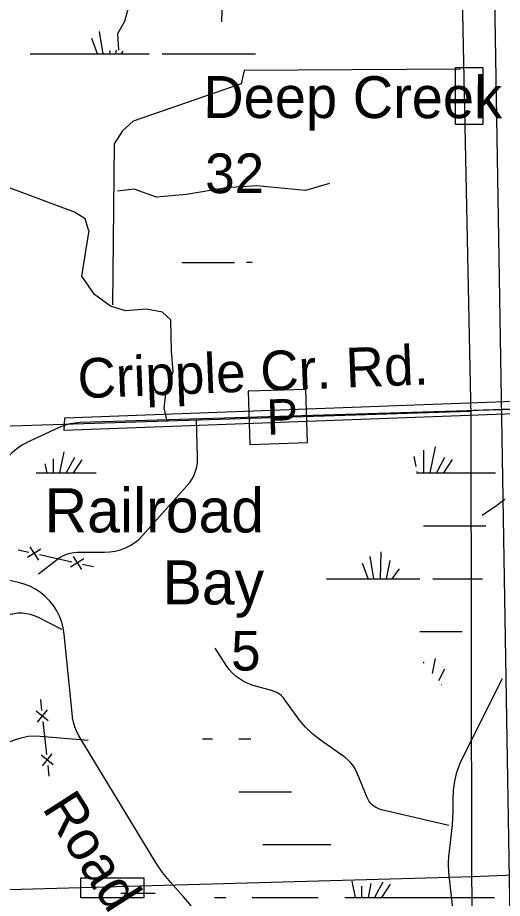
# Model space of a CAD drawing. Extents: x 2480962 to 2688785, y 277103 to 599240.
# Drawn here: x 2554432 to 2559931, y 491360 to 501349 of the extents above; entities that cross this region are included whole.
import ezdxf

# ---------------------------------------------------------------- set-up
doc = ezdxf.new("R2010")
doc.units = 0
for name, color, linetype in [('Communities and Subdivisions Names without Post Office', 7, 'Continuous'), ('Divided_Highway', 7, 'Continuous'), ('Level 31', 7, 'Continuous'), ('Local Roads Improved', 7, 'Continuous'), ('Local Roads Related Cells', 7, 'Continuous'), ('Local Roads Related Text', 7, 'Continuous'), ('Narrow River Creek and Branch and Slough', 7, 'Continuous'), ('Section Lines', 7, 'Continuous'), ('Section Numbers', 7, 'Continuous'), ('Swamps', 7, 'Continuous'), ('Swamps Text', 7, 'Continuous'), ('Township and Range lines', 7, 'Continuous'), ('Uninventoried Roads and Features', 7, 'Continuous')]:
    doc.layers.add(name, color=color, linetype=linetype)

msp = doc.modelspace()

# ---------------------------------------------------------------- linework, layer by layer
at = {"layer": 'Divided_Highway'}
msp.add_line((2560538.616, 459542.689), (2559790.472, 504995.814), dxfattribs=at)
at = {"layer": 'Level 31'}
for points in [[(2559393.459, 500139.473), (2559712.641, 500139.473), (2559712.641, 500778.116), (2559393.459, 500778.116)], [(2560873.474, 497029.239), (2560881.358, 496887.225), (2554960.204, 496666.314), (2554968.089, 496808.328)], [(2555150.221, 491592.922), (2555863.686, 491592.922), (2555863.686, 491367.518), (2555150.221, 491367.518)]]:
    msp.add_lwpolyline(points, close=True, dxfattribs=at)
at = {"layer": 'Local Roads Improved'}
for p, q in [((2555143.091, 496759.091), (2560820.969, 496932.759)), ((2554539.242, 496532.482), (2554906.61, 496703.062)), ((2554442.09, 494942.835), (2552564.902, 495363.062)), ((2555053.929, 493420.948), (2554960.46, 494357.745)), ((2556004.11, 491758.303), (2555123.39, 493212.716)), ((2556314.513, 491378.868), (2556167.97, 491539.296))]:
    msp.add_line(p, q, dxfattribs=at)
for points in [[(2554906.61, 496703.062), (2554965.409, 496726.707), (2555026.359, 496744.076), (2555088.79, 496754.98), (2555143.091, 496759.091)], [(2554287.221, 496320.239), (2554327.451, 496372.289), (2554372.902, 496419.849), (2554423.075, 496462.398), (2554477.42, 496499.468), (2554535.343, 496530.655), (2554539.242, 496532.482)], [(2554960.46, 494357.745), (2554949.895, 494426.807), (2554932.168, 494494.388), (2554907.474, 494559.745), (2554876.084, 494622.164), (2554838.341, 494680.959), (2554794.659, 494735.487), (2554745.518, 494785.15), (2554691.453, 494829.404), (2554633.059, 494867.764), (2554570.976, 494899.811), (2554505.881, 494925.192), (2554442.09, 494942.835)], [(2555123.39, 493212.716), (2555098.793, 493258.594), (2555079.127, 493306.794), (2555064.606, 493356.784), (2555055.39, 493408.018), (2555053.929, 493420.948)], [(2556167.97, 491539.296), (2556074.946, 491652.504), (2556004.11, 491758.303)], [(2556445.4, 491201.359), (2556384.688, 491293.446), (2556314.683, 491378.682), (2556314.513, 491378.868)]]:
    msp.add_lwpolyline(points, dxfattribs=at)
at = {"layer": 'Local Roads Related Cells'}
for p, q in [((2557699.766, 497132.293), (2557046.901, 497111.299)), ((2557046.901, 497111.299), (2557066.288, 496508.407)), ((2557719.153, 496529.401), (2557699.766, 497132.293)), ((2557066.288, 496508.407), (2557719.153, 496529.401))]:
    msp.add_line(p, q, dxfattribs=at)
at = {"layer": 'Narrow River Creek and Branch and Slough'}
msp.add_lwpolyline([(2559960.007, 495884.713), (2559896.26, 495836.961), (2559847.918, 495801.925), (2559774.382, 495750.738), (2559699.405, 495701.344)], dxfattribs=at)
at = {"layer": 'Section Lines'}
for p, q in [((2559578.072, 496830.483), (2559351.134, 507521.404)), ((2559582.941, 491607.864), (2559576.322, 496826.82)), ((2559582.941, 491607.864), (2564877.638, 491811.023)), ((2554334.448, 491460.787), (2559603.136, 491608.903)), ((2559687.743, 486236.799), (2559582.949, 491607.864)), ((2557091.943, 491369.855), (2557541.942, 491369.862))]:
    msp.add_line(p, q, dxfattribs=at)
at = {"layer": 'Swamps'}
for p, q in [((2555401.328, 500938.471), (2555361.933, 501191.705)), ((2555339.006, 500939.393), (2555272.935, 501112.187)), ((2555479.49, 500938.428), (2555480.178, 500974.968)), ((2555546.588, 500938.22), (2555555.066, 500978.912)), ((2555608.784, 500937.913), (2555630.716, 500967.678)), ((2554573.327, 500938.395), (2555173.326, 500938.404)), ((2555173.326, 500938.404), (2555923.325, 500938.416)), ((2556293.032, 498572.3), (2556893.031, 498572.309)), ((2559034.088, 496444.193), (2559034.092, 496185.632)), ((2559166.993, 496480.441), (2559108.056, 496185.738)), ((2555075.742, 496359.555), (2554981.737, 496184.968)), ((2559275.734, 496359.621), (2559181.728, 496185.034)), ((2555160.318, 496335.392), (2555061, 496186.411)), ((2559360.31, 496335.457), (2559260.992, 496186.477)), ((2558549.326, 494985.647), (2558555.053, 495289.36)), ((2558408.843, 494986.612), (2558342.771, 495159.406)), ((2558471.165, 494985.69), (2558431.77, 495238.924)), ((2558616.425, 494985.439), (2558659.309, 495191.29)), ((2558678.621, 494985.132), (2558762.398, 495098.833)), ((2558243.163, 494985.623), (2558993.161, 494985.635)), ((2558224.143, 491555.94), (2558261.354, 491369.895)), ((2558659.105, 491519.7), (2558559.787, 491370.72)), ((2557541.942, 491369.862), (2557841.941, 491369.867)), ((2558141.941, 491369.871), (2559841.937, 491369.898))]:
    msp.add_line(p, q, dxfattribs=at)
for points in [[(2556073.325, 500938.418), (2557128.576, 500938.434)], [(2557027.947, 498574.929), (2557090.916, 498574.93)], [(2554834.098, 496346.381), (2554834.1, 496185.566)], [(2554956.061, 496425.672), (2554908.064, 496185.672)], [(2558925.348, 496371.698), (2558947.884, 496259.023)], [(2554742.339, 496286.727), (2554762.568, 496185.587)], [(2554643.154, 496185.563), (2555320.942, 496185.573)], [(2558957.204, 496185.631), (2559851.815, 496185.645)], [(2558959.492, 496200.991), (2558962.56, 496185.653)], [(2559035.921, 495585.634), (2559743.152, 495585.645)], [(2557935.487, 494985.618), (2558243.163, 494985.623)], [(2559143.161, 494985.637), (2559703.348, 494985.646)], [(2558993.169, 494385.636), (2559474.375, 494385.644)], [(2559167.024, 494080.448), (2559133.336, 493912.003)], [(2559034.12, 494044.2), (2559034.12, 494028.268)], [(2559275.765, 493959.628), (2559204.941, 493828.094)], [(2559241.168, 493785.642), (2559245.403, 493785.642)], [(2556529.716, 493169.841), (2556641.92, 493169.843)], [(2556941.92, 493169.847), (2557077.023, 493169.85)], [(2556941.928, 492569.849), (2557538.354, 492569.858)], [(2557214.041, 491969.855), (2557541.934, 491969.86)], [(2557541.934, 491969.86), (2557985.917, 491969.867)], [(2558332.885, 491497.56), (2558332.886, 491369.874)], [(2558438.393, 491527.708), (2558406.85, 491369.981)], [(2558574.529, 491543.864), (2558480.523, 491369.277)], [(2555604.222, 491419.348), (2555993.387, 491419.354)], [(2556664.062, 491369.848), (2556791.944, 491369.85)]]:
    msp.add_lwpolyline(points, dxfattribs=at)
at = {"layer": 'Township and Range lines'}
for p, q in [((2564798.394, 497066.643), (2559603.69, 496894.703)), ((2559566, 496880.961), (2554237.072, 496711.546))]:
    msp.add_line(p, q, dxfattribs=at)
at = {"layer": 'Uninventoried Roads and Features'}
for p, q in [((2556781.287, 502955.57), (2556746.323, 501302.052)), ((2556473.419, 496360.941), (2556460.568, 496795.997)), ((2555852.416, 495479.358), (2556356.222, 496040.785)), ((2554572.198, 495346.17), (2554667.312, 495197.162)), ((2554436.663, 495312.086), (2554558.724, 495285.139)), ((2554694.259, 495319.223), (2554545.251, 495224.109)), ((2554680.786, 495258.192), (2555046.969, 495177.352)), ((2555117.064, 495284.836), (2555417.586, 495285.095)), ((2554669.974, 495042.563), (2554882.953, 495205.457)), ((2555182.504, 495211.436), (2555033.496, 495116.322)), ((2555060.442, 495238.383), (2555155.557, 495089.375)), ((2555169.03, 495150.406), (2555291.091, 495123.459)), ((2554934.614, 494410.635), (2554667.612, 494545.617)), ((2556803.05, 493997.318), (2556671.663, 494199.367)), ((2559481.829, 492959.123), (2559933.752, 493852.008)), ((2557311.199, 493719.084), (2557105.307, 493776.012)), ((2554689.609, 493613.756), (2554703.585, 493489.54)), ((2557612.175, 493406.812), (2557464.64, 493612.128)), ((2554779.669, 493372.312), (2554641.477, 493482.552)), ((2554765.693, 493496.528), (2554655.453, 493358.336)), ((2554717.561, 493365.324), (2554759.49, 492992.676)), ((2555232.861, 493149.78), (2554688.255, 493196.879)), ((2558131.775, 492970.327), (2557867.011, 493155.324)), ((2554835.574, 492875.448), (2554697.382, 492985.688)), ((2554821.598, 492999.664), (2554711.358, 492861.472)), ((2554773.466, 492868.46), (2554787.443, 492744.244)), ((2558396.73, 492504.401), (2558283.104, 492781.323)), ((2559373.906, 492392.468), (2559372.071, 492475.681)), ((2559324.943, 492185.806), (2558560.117, 492365.136)), ((2559325.205, 491860.344), (2559364.355, 492192.307)), ((2559367.322, 491248.753), (2559324.096, 491652.17))]:
    msp.add_line(p, q, dxfattribs=at)
for points in [[(2555578.401, 500980.918), (2555567.878, 501167.725), (2555647.069, 501308.473), (2555680.435, 501434.622), (2555777.527, 501552.658), (2555961.759, 501574.431), (2556069.289, 501584.724), (2556122.774, 501676.645)], [(2559456.681, 500765.378), (2557000.94, 500750.837), (2556968.211, 500599.634), (2555741.328, 500174.878), (2555622.88, 500064.044), (2555528.446, 499917.146), (2555509.433, 498090.451)], [(2556128.132, 496770.803), (2556093.581, 496918.466), (2556114.474, 497080.955), (2556151.834, 497201.416), (2556196.692, 497329.769), (2556177.201, 497566.5), (2556170.11, 497921.165), (2556073.597, 498007.558), (2555893.666, 498043.74), (2555657.446, 498022.648), (2555486.742, 498074.479), (2555304.312, 498208.952), (2555158.544, 498415.657), (2555241.599, 498934.473), (2555237.604, 498940.162), (2555199.745, 499066.532), (2555076.545, 499142.643), (2554328.335, 499423.609), (2554276.08, 499586.274), (2554267.372, 500004.537), (2554201.204, 500714.547)], [(2557969.013, 499468.496), (2557697.712, 499388.708), (2557142.026, 499440.949), (2556796.107, 499419.153), (2556345.758, 499340.857), (2556007.68, 499313.464), (2555755.201, 499401.903), (2555565.149, 499381.918)], [(2556356.222, 496040.785), (2556386.399, 496078.178), (2556412.502, 496118.522), (2556434.245, 496161.372), (2556451.389, 496206.26), (2556463.748, 496252.695), (2556471.185, 496300.167), (2556473.62, 496348.157), (2556473.419, 496360.941)], [(2555417.586, 495285.095), (2555478.724, 495288.352), (2555539.186, 495297.982), (2555598.311, 495313.879), (2555655.45, 495335.87), (2555709.977, 495363.712), (2555761.296, 495397.102), (2555808.842, 495435.672), (2555852.097, 495479.002), (2555852.416, 495479.358)], [(2554882.953, 495205.457), (2554916.277, 495228.285), (2554951.806, 495247.503), (2554989.15, 495262.903), (2555027.898, 495274.314), (2555067.626, 495281.613), (2555107.9, 495284.72), (2555117.064, 495284.836)], [(2554667.613, 494545.617), (2554624.537, 494564.633), (2554579.709, 494579.041), (2554533.621, 494588.685), (2554486.777, 494593.459), (2554439.691, 494593.31), (2554392.878, 494588.24), (2554346.852, 494578.305), (2554302.117, 494563.612), (2554259.162, 494544.324), (2554218.458, 494520.652), (2554180.453, 494492.855), (2554150.715, 494466.342)], [(2557105.307, 493776.012), (2557052.826, 493793.528), (2557002.464, 493816.434), (2556954.771, 493844.478), (2556910.27, 493877.353), (2556869.451, 493914.7), (2556832.758, 493956.109), (2556803.05, 493997.318)], [(2557464.64, 493612.128), (2557446.233, 493635.103), (2557425.526, 493656.028), (2557402.746, 493674.674), (2557378.141, 493690.836), (2557351.981, 493704.338), (2557324.554, 493715.032), (2557311.199, 493719.084)], [(2557867.011, 493155.324), (2557779.112, 493223.856), (2557698.859, 493301.202), (2557627.13, 493386.513), (2557612.175, 493406.812)], [(2554688.255, 493196.879), (2554619.548, 493199.21), (2554550.973, 493194.346), (2554483.284, 493182.34), (2554417.219, 493163.325), (2554353.503, 493137.508), (2554292.836, 493105.173), (2554235.882, 493066.673), (2554183.262, 493022.43), (2554135.556, 492972.931), (2554093.286, 492918.715), (2554056.914, 492860.379), (2554026.84, 492798.559), (2554003.392, 492733.935), (2553986.827, 492667.214), (2553977.327, 492599.126), (2553974.904, 492547.633)], [(2558283.104, 492781.323), (2558263.887, 492821.958), (2558240.529, 492860.363), (2558213.284, 492896.115), (2558182.45, 492928.825), (2558148.367, 492958.131), (2558131.775, 492970.327)], [(2559372.071, 492475.681), (2559375.309, 492582.471), (2559389.693, 492688.338), (2559415.063, 492792.123), (2559451.143, 492892.686), (2559481.829, 492959.123)], [(2558560.117, 492365.136), (2558536.55, 492371.981), (2558513.827, 492381.252), (2558492.198, 492392.848), (2558471.899, 492406.641), (2558453.153, 492422.479), (2558436.166, 492440.191), (2558421.123, 492459.582), (2558408.19, 492480.438), (2558397.507, 492502.533), (2558396.73, 492504.401)], [(2559364.355, 492192.307), (2559374.139, 492342.538), (2559373.906, 492392.468)], [(2559324.096, 491652.17), (2559318.801, 491749.45), (2559323.703, 491846.751), (2559325.205, 491860.344)]]:
    msp.add_lwpolyline(points, dxfattribs=at)

# ---------------------------------------------------------------- texts
at = {"layer": 'Communities and Subdivisions Names without Post Office'}
msp.add_text('Deep Creek', height=475, rotation=359.9502028, dxfattribs=at).set_placement((2556537.253, 500210.836))
at = {"layer": 'Local Roads Related Text'}
for s, height, rotation, p in [('Cripple Cr. Rd.', 450, 2.2922083, (2555121.065, 497030.302)), ('P', 400, 1.8418028, (2557262.274, 496618.018)), ('Road', 450, 302.6120639, (2554702.478, 492382.946))]:
    msp.add_text(s, height=height, rotation=rotation, dxfattribs=at).set_placement(p)
at = {"layer": 'Section Numbers'}
for s, rotation, p in [('32', 359.9793917, (2556558.881, 499358.413)), ('5', 359.9794, (2556853.304, 493944.243))]:
    msp.add_text(s, height=450, rotation=rotation, dxfattribs=at).set_placement(p)
at = {"layer": 'Swamps Text'}
for s, rotation, p in [('Railroad', 359.9502083, (2554737.46, 495511.847)), ('Bay', 359.9502111, (2556075.57, 494693.668))]:
    msp.add_text(s, height=500, rotation=rotation, dxfattribs=at).set_placement(p)

doc.saveas('drawing.dxf')
